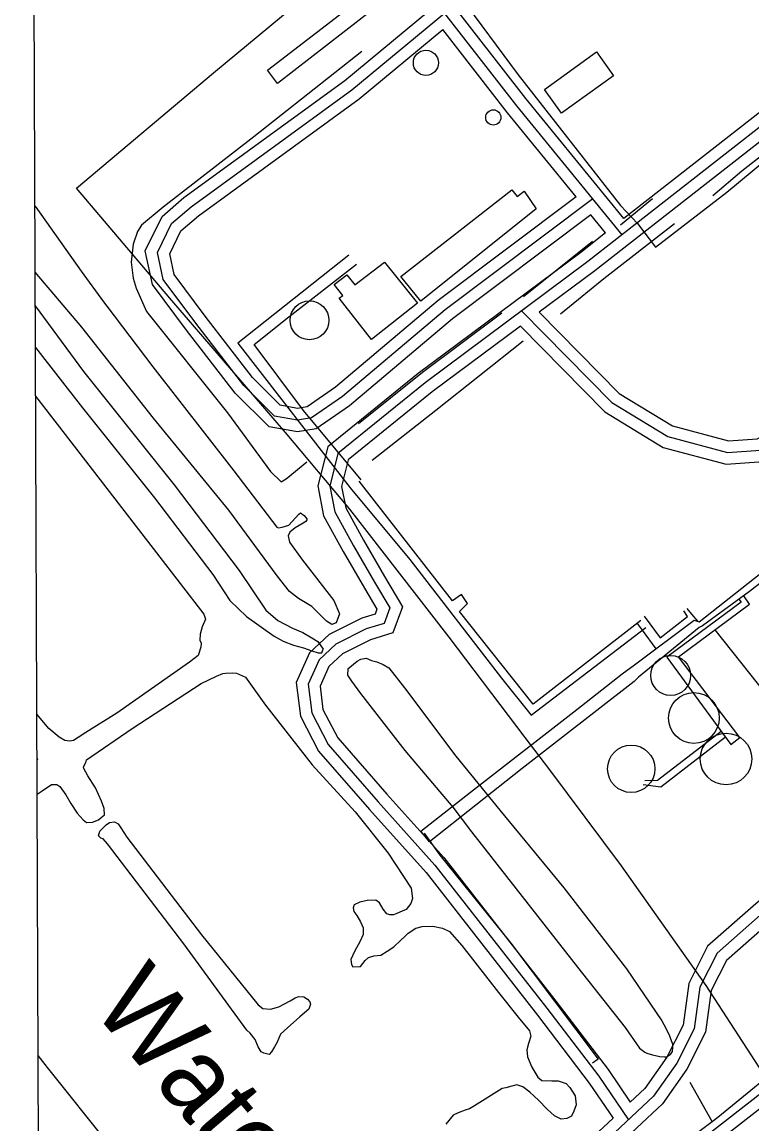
# Model space of a CAD drawing. Extents: x 3405885 to 3443815, y 558517 to 583997.
# Drawn here: x 3409954 to 3410898, y 576200 to 577623 of the extents above; entities that cross this region are included whole.
import ezdxf

# ---------------------------------------------------------------- set-up
doc = ezdxf.new("R2010")
doc.units = 0
for name, color, linetype in [('V-BLDG-OTLN', 7, 'Continuous'), ('V-DOMW-TANK', 7, 'Continuous'), ('V-GRID-FRAM', 7, 'Continuous'), ('V-RIVR-IDEN', 7, 'Continuous'), ('V-ROAD-CNTR', 7, 'Continuous'), ('V-SITE-OTLN', 7, 'Continuous'), ('V-TOPO-SHOR', 7, 'Continuous'), ('V-UTIL-LINE', 7, 'Continuous')]:
    doc.layers.add(name, color=color, linetype=linetype)

msp = doc.modelspace()

# ---------------------------------------------------------------- linework, layer by layer
at = {"layer": 'V-BLDG-OTLN'}
for points in [[(3410271.4, 577560.9), (3410397.9, 577658.9), (3410411.1, 577641.9), (3410284.4, 577543.8)], [(3410629.4, 577536.2), (3410696.7, 577584.6), (3410718.8, 577553.8), (3410651.3, 577505.4)], [(3410443.7, 577294.6), (3410587.4, 577406.5), (3410594.1, 577397.8), (3410603, 577404.7), (3410618.7, 577382.1), (3410469.4, 577262.7)], [(3410465.3, 577259.8), (3410405.6, 577213.1), (3410364, 577266.3), (3410368.6, 577269.9), (3410357.7, 577284), (3410374, 577296.8), (3410384.3, 577283.7), (3410422.6, 577313)]]:
    msp.add_lwpolyline(points, close=True, dxfattribs=at)
at = {"layer": 'V-DOMW-TANK'}
for centre, radius in [((3410476.1, 577570.5), 16.2), ((3410563.3, 577500), 9.84), ((3410325.6, 577237.9), 25.1), ((3410792.6, 576779), 25.8), ((3410822.6, 576724), 32.8), ((3410864.2, 576671.1), 33.3), ((3410741.6, 576658.4), 30.6)]:
    msp.add_circle(centre, radius, dxfattribs=at)
at = {"layer": 'V-GRID-FRAM'}
msp.add_lwpolyline([(3409954, 582088.9), (3441575.2, 582215.4), (3441655.9, 564032.2), (3410018.8, 563905.7), (3409954, 582088.9)], dxfattribs=at)
at = {"layer": 'V-ROAD-CNTR'}
for points in [[(3410729.8, 577348.3), (3410593.5, 577515.1), (3410427.7, 577728.1), (3410388.1, 577781.4), (3410372.8, 577812.5), (3410373.7, 577836.8), (3410386.6, 577857.6), (3410437.1, 577900), (3410795.1, 578180.8), (3411245.4, 578530.4), (3411873.5, 579019.9), (3412386.4, 579417.5), (3412669.1, 579639.2), (3412713.8, 579669.1), (3412750.2, 579689.7), (3412768.7, 579699.8)], [(3410732.2, 577369.2), (3410605.2, 577524.5), (3410439.7, 577737.1), (3410401, 577789.3), (3410387.9, 577815.7), (3410388.6, 577832.2), (3410398.1, 577847.7), (3410446.5, 577888.4), (3410804.3, 578169), (3411254.6, 578518.5), (3411882.7, 579008.1), (3412395.6, 579405.7), (3412677.9, 579627.1), (3412721.7, 579656.3), (3412757.5, 579676.6), (3412775.9, 579686.6)], [(3412925.9, 579068.1), (3412738, 578925.4), (3412562.6, 578790.9), (3412341.7, 578623.2), (3411769.3, 578175.8), (3411462.4, 577937.5), (3411013.6, 577589.1), (3410732.2, 577369.2)], [(3413210.3, 578015.5), (3413107.9, 577931.8), (3412854.6, 577735.4), (3412414.8, 577392.8), (3411978.8, 577052), (3411481.9, 576669), (3411109.6, 576376.2), (3410592.3, 575973.2), (3410440.1, 575851.4), (3410435.1, 575850.6)], [(3411471.6, 577925.6), (3411022.8, 577577.3), (3410685.6, 577313.7), (3410475.2, 577157.1), (3410362.5, 577065.9), (3410351.8, 577023.6), (3410358.2, 576990.3), (3410382.4, 576946.5), (3410409.7, 576899.4), (3410429.3, 576866.2), (3410422.1, 576846), (3410399, 576839.1), (3410359.7, 576819.6), (3410338.1, 576799.3), (3410324, 576767.6), (3410328.5, 576730.7), (3410349.8, 576689.8), (3410414.4, 576615.6), (3410487.9, 576534), (3410632.3, 576349.1), (3410699.6, 576261.1), (3410737.9, 576204.9), (3410737, 576207.2)], [(3410689.3, 577374.2), (3410510.6, 577239.8), (3410377.4, 577127.5), (3410334.1, 577097.8), (3410310.2, 577093.6), (3410273.3, 577100.2), (3410229.4, 577143.9), (3410166.8, 577225.2), (3410122.5, 577284.2), (3410113.4, 577327.5), (3410135.1, 577372.1), (3410163.4, 577396.4), (3410371.3, 577547.5), (3410479.5, 577637.1)], [(3410691.8, 577394.9), (3410501.2, 577251.5), (3410368.3, 577139.5), (3410328.3, 577112), (3410310.2, 577108.8), (3410280.5, 577114.1), (3410240.7, 577153.8), (3410178.7, 577234.2), (3410136.5, 577290.6), (3410129.1, 577325.6), (3410147.2, 577362.8), (3410172.7, 577384.6), (3410380.5, 577535.6), (3410500.3, 577634.8), (3410501, 577633.5)], [(3410670.3, 577397.5), (3410491.9, 577263.3), (3410359.2, 577151.4), (3410322.5, 577126.2), (3410310.2, 577124), (3410287.8, 577128.1), (3410252, 577163.8), (3410190.6, 577243.3), (3410150.5, 577296.9), (3410144.9, 577323.6), (3410159.3, 577353.4), (3410182, 577372.8), (3410389.7, 577523.8), (3410498, 577613.4)], [(3410670.3, 577397.5), (3410581.7, 577505.8), (3410498, 577613.4)], [(3410992.9, 577534.9), (3410694.7, 577301.8), (3410622.7, 577248.2)], [(3410708.5, 577350.7), (3410689.3, 577374.2)], [(3410708.5, 577350.7), (3410676.5, 577325.6), (3410466, 577169), (3410349.2, 577074.4), (3410336.5, 577024), (3410343.9, 576985.1), (3410369.3, 576939.1), (3410396.8, 576891.8), (3410412.8, 576864.6), (3410410.5, 576858.2), (3410393.5, 576853.1), (3410351, 576832.1), (3410325.6, 576808.2), (3410308.6, 576769.9), (3410314, 576726.2), (3410337.3, 576681.3), (3410403.1, 576605.7), (3410476.4, 576524.4), (3410620.5, 576340), (3410687.4, 576252.3), (3410718.3, 576207.1)], [(3410622.7, 577248.2), (3410726, 577143.5), (3410795.1, 577101.6), (3410867.4, 577082.2), (3410904.5, 577084.8), (3410952.7, 577109.5), (3411021.4, 577171.4), (3411084.2, 577228.4), (3411130.8, 577263.4), (3411180.9, 577294)], [(3410604.3, 577253.2), (3410599.9, 577250), (3410716.6, 577131.6), (3410789.1, 577087.6), (3410866, 577067), (3410908.6, 577070), (3410961.3, 577097), (3411031.4, 577160.3), (3411093.8, 577216.8), (3411139.2, 577251), (3411203, 577290), (3411201.9, 577290)], [(3410598.4, 577230.1), (3410707.3, 577119.8), (3410783.1, 577073.7), (3410864.5, 577051.9), (3410912.7, 577055.3), (3410969.9, 577084.6), (3411041.5, 577149.1), (3411103.3, 577205.2), (3411147.7, 577238.5), (3411199.4, 577270.2)], [(3410598.4, 577230.1), (3410484.4, 577145.3), (3410375.8, 577057.4), (3410367.2, 577023.1), (3410372.5, 576995.4), (3410395.4, 576953.9), (3410422.7, 576907), (3410445.7, 576867.7), (3410433.6, 576833.9), (3410404.6, 576825.1), (3410368.3, 576807.1), (3410350.6, 576790.5), (3410339.4, 576765.3), (3410343.1, 576735.2), (3410362.3, 576698.3), (3410425.6, 576625.6), (3410499.4, 576543.7), (3410644.2, 576358.3), (3410711.8, 576269.9), (3410740.4, 576227.8)], [(3411375.4, 577065.1), (3411375.8, 577066.8), (3411284.4, 576987.8), (3411176.8, 576892.7), (3411144.4, 576832), (3411121.8, 576775.8), (3411111.5, 576718), (3411095, 576658.8), (3411070.8, 576608.1), (3411017.4, 576558.9), (3410912.3, 576472.6), (3410852.5, 576420.1), (3410830.4, 576376.4), (3410823.1, 576322.5), (3410800.5, 576277.9), (3410770.6, 576235.6), (3410684.7, 576155)], [(3411355.2, 577068.8), (3411274.5, 576999.1), (3411164.8, 576902.2), (3411130.8, 576838.3), (3411107.3, 576779.9), (3411096.9, 576721.3), (3411080.9, 576664.1), (3411058.5, 576617.2), (3411007.6, 576570.3), (3410902.6, 576484.1), (3410840.4, 576429.4), (3410815.9, 576380.9), (3410808.6, 576327), (3410787.7, 576285.7), (3410759.2, 576245.5), (3410740.4, 576227.8)], [(3411373.6, 577045.1), (3411294.2, 576976.5), (3411188.7, 576883.3), (3411158.1, 576825.6), (3411136.3, 576771.6), (3411126.2, 576714.6), (3411109.1, 576653.5), (3411083, 576599.1), (3411027.3, 576547.6), (3410922, 576461.2), (3410864.6, 576410.7), (3410844.9, 576371.9), (3410837.6, 576318), (3410813.4, 576270.2), (3410782, 576225.7), (3410694.4, 576143.6), (3410516.6, 576006.7), (3410392.1, 575904.4)], [(3411590.1, 576771.3), (3411472.7, 576680.8), (3411100.3, 576388), (3410583, 575985), (3410439.1, 575869.8)], [(3410718.3, 576207.1), (3410674.9, 576166.5), (3410497.9, 576030.1), (3410342.6, 575902.6), (3410276.7, 575855.8), (3410238.5, 575819.4), (3410189.2, 575753.6), (3410121.9, 575679.2), (3410048.5, 575608.1), (3409988.5, 575544.4)]]:
    msp.add_lwpolyline(points, dxfattribs=at)
at = {"layer": 'V-SITE-OTLN'}
for points in [[(3410444.8, 577758.9), (3410595.5, 577555.1), (3410727.8, 577386.4), (3410749.5, 577363.1), (3410773.1, 577332.5), (3410865.4, 577403.3), (3410983.6, 577501.6), (3410998.3, 577514.1)], [(3410977.6, 576142.3), (3410922.8, 576248.4), (3410838.4, 576378.5), (3410729.1, 576533.2), (3410636.3, 576657.1), (3410604.5, 576698.8), (3410506.2, 576828.3), (3410377.8, 576993.7), (3410294.5, 577092.7), (3410144.9, 577266.6), (3410024.3, 577408.8), (3410201.7, 577557.7), (3410392.4, 577716.3)]]:
    msp.add_lwpolyline(points, dxfattribs=at)
at = {"layer": 'V-TOPO-SHOR'}
for p, q in [((3410727.9, 577361.1), (3410769.1, 577395.3)), ((3410602.2, 577268.7), (3410691.4, 577340.2)), ((3410341.6, 576808.3), (3410343.2, 576813)), ((3410375.4, 576787.7), (3410374.7, 576779.4)), ((3410817.5, 576253.4), (3410846.2, 576202.4))]:
    msp.add_line(p, q, dxfattribs=at)
for points in [[(3410393.2, 577585), (3410253.6, 577474.8), (3410136.5, 577384.2), (3410108.6, 577360.6), (3410103.2, 577352.7), (3410097.8, 577336.2), (3410095, 577313), (3410097.6, 577292.5), (3410101.4, 577279.3), (3410115.1, 577249.4), (3410219.5, 577118.4), (3410275.2, 577042.6), (3410289, 577029.2), (3410295.7, 577033.2), (3410322.3, 577054.8)], [(3411073.3, 577398.5), (3411013.8, 577472.9), (3410997, 577497.5), (3410991.3, 577502.8), (3410986.6, 577504), (3410979.6, 577504.1), (3410959.1, 577488.5), (3410884.7, 577430.6), (3410847.2, 577398.8)], [(3409970.8, 577385.5), (3410030.6, 577301.4), (3410059.3, 577261.8), (3410063.5, 577256.2)], [(3410797.4, 577362.4), (3410706, 577291.3), (3410650.3, 577245.6)], [(3410063.5, 577256.2), (3410123.1, 577177.7), (3410228, 577043.5), (3410283.6, 576970.5), (3410285.6, 576969.8), (3410290.5, 576970.5), (3410298.8, 576973.2), (3410312, 576987.6), (3410314.1, 576989), (3410318.9, 576985.5), (3410322.4, 576981.4), (3410322.4, 576980), (3410321, 576977.9), (3410317.5, 576975.9), (3410307.1, 576969.7), (3410300.1, 576964.2), (3410298, 576959.4), (3410300, 576951.1), (3410316.5, 576928.1), (3410356.9, 576876), (3410364.4, 576858.7), (3410360.2, 576846.9), (3410354.7, 576844.9), (3410347.8, 576849.1), (3410328.5, 576867.9), (3410311.3, 576878.4), (3410299.6, 576887.5), (3410283.9, 576907.6), (3410221.5, 576992.4), (3410124.1, 577111.3), (3410031.5, 577228.8), (3409971.1, 577299.9)], [(3409971.2, 577256.4), (3410033.5, 577171.7), (3410150.5, 577025.5), (3410234.8, 576914.6), (3410269.1, 576863.4), (3410284.8, 576849.8), (3410303.5, 576840.3), (3410317, 576834.3), (3410328.7, 576827.8), (3410336.3, 576823), (3410343.2, 576813)], [(3410388.8, 577104.7), (3410471.9, 577171), (3410574.3, 577247.7)], [(3410601.7, 577211), (3410489.1, 577121.4), (3410406.5, 577056.6)], [(3409971.4, 577202.7), (3410032, 577124.8), (3410125.1, 577008.6), (3410200.7, 576909.6), (3410222.8, 576876), (3410244.4, 576855.3), (3410280, 576829.9), (3410291.7, 576823.3), (3410305.1, 576818), (3410318, 576814.9), (3410328.6, 576810.8), (3410336.8, 576808.4)], [(3409971.6, 577139.7), (3410009.7, 577090.3), (3410128, 576937.5), (3410188.9, 576858.1), (3410191.2, 576851.7), (3410187.1, 576841.7), (3410184.1, 576832.4), (3410184, 576824.8), (3410185.8, 576820.7), (3410185.1, 576815.4), (3410181.6, 576804.9), (3410170.4, 576796.2), (3410076.4, 576730.2), (3410036.4, 576705.3), (3410026.4, 576698.9), (3410020.6, 576694.8), (3410015.3, 576694.3), (3410009.4, 576694.9), (3410001.9, 576699.1), (3409988.5, 576710.3), (3409973.1, 576729)], [(3410336.8, 576808.4), (3410341.6, 576808.3), (3410343.2, 576813)], [(3410375.4, 576787.7), (3410387.3, 576797.3), (3410392.1, 576800), (3410398.9, 576801.5)], [(3410398.9, 576801.5), (3410405.9, 576798.5), (3410412.9, 576796.7), (3410421.1, 576793.1), (3410428.1, 576789), (3410448.5, 576763), (3410514.8, 576674.6), (3410571.8, 576605), (3410654.5, 576504.8), (3410735.3, 576399.8), (3410781.2, 576332.6), (3410786.4, 576323.2), (3410791, 576313.2), (3410793.4, 576307.3), (3410795.1, 576303.2), (3410795.1, 576298.5), (3410794.4, 576293.2), (3410792.1, 576289.2)], [(3409973.5, 576625.7), (3409980.1, 576630.1), (3409992.3, 576638.2), (3409998.8, 576638.2), (3410002.7, 576635.4), (3410010.8, 576624.9), (3410017.3, 576613.4), (3410025.5, 576601.2), (3410033.1, 576592.4), (3410037.4, 576589.1), (3410045.1, 576589.6), (3410052.8, 576592.3), (3410056.1, 576595.6), (3410060.5, 576598.8), (3410060, 576607.1), (3410056.8, 576616.4), (3410049.2, 576634), (3410038.9, 576649.4), (3410034.1, 576658.7), (3410033.5, 576660.9), (3410036.3, 576666.4), (3410037.4, 576670.2), (3410096.3, 576710.4), (3410185.5, 576768.5), (3410205.3, 576778.2), (3410213.6, 576781.4), (3410216.9, 576782), (3410225.6, 576782.5), (3410231.1, 576781.9), (3410243.1, 576776.9), (3410268.7, 576740.5), (3410329, 576663.4), (3410384.5, 576602.7), (3410427.5, 576549.3), (3410457.3, 576504.1), (3410458.9, 576491), (3410456.6, 576484.4), (3410450.6, 576476.8), (3410445.6, 576474.6), (3410438.5, 576471.4), (3410434.1, 576469.7), (3410429.7, 576469.8), (3410425.8, 576470.9), (3410421, 576477), (3410416.1, 576485.2), (3410411.2, 576488.5), (3410400.2, 576488.1), (3410390.9, 576485.9), (3410383.2, 576482.7), (3410382, 576478.9), (3410383.1, 576473.9), (3410386.9, 576469), (3410391.8, 576460.7), (3410395, 576453), (3410395, 576444.2), (3410391.1, 576435.5), (3410383.9, 576422.4), (3410378.9, 576412)], [(3410374.7, 576779.4), (3410379.9, 576771.7), (3410391.5, 576755.8), (3410449.1, 576682.1), (3410510.8, 576608.9), (3410535.3, 576577.1), (3410592.9, 576503.4), (3410672, 576402), (3410733.6, 576324.1), (3410752.2, 576297.6), (3410759.2, 576292.3), (3410761.6, 576291.1), (3410769.2, 576288.7), (3410778.6, 576286.9), (3410784.4, 576286.3), (3410787.3, 576286.2), (3410792.1, 576289.2)], [(3409973.3, 576672.4), (3409974.2, 576670.6), (3409973.3, 576669.4)], [(3410244.5, 576320.8), (3410163, 576432.1), (3410064.7, 576561.5), (3410058.7, 576568.1), (3410055.9, 576568.7), (3410052.7, 576572), (3410054.4, 576578), (3410062.6, 576586.2), (3410067, 576588.9), (3410073.6, 576590), (3410078.5, 576587.2), (3410081.8, 576582.2), (3410089.4, 576570.1), (3410186.1, 576444), (3410259.5, 576353.6), (3410265.5, 576348.6), (3410275.4, 576348), (3410285.8, 576350.7), (3410300.7, 576358.8), (3410307.3, 576362.6), (3410311.7, 576364.2), (3410318.2, 576363.6), (3410323.2, 576360.8), (3410325.9, 576357.5), (3410327, 576354.2), (3410324.7, 576347.7), (3410313.1, 576337.9), (3410297.2, 576323.7), (3410288.3, 576315.6), (3410283.9, 576305.2), (3410280.5, 576299.2), (3410276.7, 576292.6), (3410273.4, 576289.4), (3410266.8, 576291), (3410263, 576292.7), (3410259.2, 576299.3), (3410255.4, 576308.7), (3410248.9, 576316.9), (3410244.5, 576320.8)], [(3410378.9, 576412), (3410379.9, 576405.4), (3410381.5, 576402.7), (3410391.4, 576403.1), (3410397.5, 576410.8), (3410401.9, 576414.6), (3410409, 576416.7), (3410417.8, 576417.8), (3410426.1, 576422.7), (3410434.9, 576428.6), (3410443.7, 576436.8), (3410448.7, 576441.7), (3410453.1, 576446), (3410463, 576452.6), (3410471.2, 576454.7), (3410484.9, 576455.2), (3410497.5, 576452.3), (3410506.8, 576448.4), (3410522.6, 576430.2), (3410569.9, 576369.6), (3410595.4, 576337.7), (3410610.1, 576320), (3410611.7, 576312.9), (3410608.9, 576303.6), (3410606.7, 576295.4), (3410607.7, 576286.1), (3410613.1, 576272.9), (3410620.7, 576260.2), (3410626.1, 576255.8), (3410638.8, 576255.2), (3410647, 576255.1), (3410657.4, 576251.7), (3410662.3, 576246.8), (3410669.3, 576235.8), (3410670.3, 576224.3), (3410667.5, 576216.1), (3410664.2, 576209.5), (3410658.2, 576206.8), (3410651, 576205.7), (3410642.3, 576210.2), (3410633, 576218.5), (3410621.6, 576230.1), (3410610.7, 576240.5), (3410601.4, 576247.7), (3410593.8, 576250), (3410587.2, 576248.4), (3410579.5, 576246.2), (3410574.6, 576245.2)], [(3411122.2, 576422.8), (3410955.7, 576291.5), (3410853.6, 576208), (3410846.2, 576202.4), (3410672.5, 576072), (3410454.8, 575899.9), (3410416.2, 575864.6)], [(3410067.6, 576171.8), (3409987.1, 576272.6), (3409974.7, 576288)], [(3410574.6, 576245.2), (3410538.8, 576222.9), (3410532.7, 576219.1), (3410526.7, 576217.5), (3410517.9, 576213.8), (3410511.3, 576211.1), (3410501.9, 576199.1)]]:
    msp.add_lwpolyline(points, dxfattribs=at)
at = {"layer": 'V-UTIL-LINE'}
msp.add_line((3410849.8, 576838.1), (3410927.9, 576739.6), dxfattribs=at)
for points in [[(3410376.6, 577321.9), (3410232.9, 577208.5), (3410378.2, 577021.3)], [(3410392.5, 577031.7), (3410317.9, 577121.2), (3410254.1, 577206.5), (3410298.9, 577242.2), (3410386.5, 577310.5)], [(3410753.9, 576849.8), (3410614.7, 576741.7), (3410519.6, 576861.6), (3410529.9, 576872), (3410522, 576883.7), (3410510.6, 576875.3), (3410390, 577029.9)], [(3411020.6, 576985.2), (3410894.4, 576887.6), (3410883.1, 576879.1), (3410833.9, 576843.1), (3410829.3, 576841.1), (3410750.9, 576776.9), (3410745.6, 576771), (3410600.8, 576658.9), (3410480.6, 576563.9), (3410469.4, 576577.9), (3410533.9, 576628.3), (3410671.3, 576735.1), (3410729.8, 576781), (3410745.7, 576792.8), (3410822.8, 576850.4), (3410829.4, 576848.4), (3411060.5, 577030.6)], [(3410378.2, 577021.3), (3410455.2, 576928.7), (3410573.9, 576775.4), (3410612.4, 576727.9), (3410760.5, 576841.1)], [(3410880.9, 576877.5), (3410883.6, 576873.5), (3410787.7, 576802.8), (3410870.3, 576689.8), (3410882, 576698.8), (3410802.5, 576803.2), (3410894.3, 576870.9), (3410887, 576882)], [(3410758.2, 576855.6), (3410779.2, 576827.5), (3410814.5, 576855.2), (3410809.5, 576862.6)], [(3410813.4, 576865.5), (3410819.7, 576858.2), (3410827.9, 576848.8)], [(3410749.3, 576846.3), (3410755.7, 576837.4), (3410773.3, 576813.4)], [(3410863.4, 576699.2), (3410780, 576634.8), (3410757.2, 576637.7)], [(3410759.1, 576643.1), (3410775.5, 576643.9), (3410857.7, 576707)], [(3410473.8, 576575.1), (3410494, 576547), (3410586.1, 576433.2), (3410699, 576283.2), (3410691.4, 576278)]]:
    msp.add_lwpolyline(points, dxfattribs=at)

# ---------------------------------------------------------------- texts
at = {"layer": 'V-RIVR-IDEN'}
msp.add_text('Water', height=100, rotation=310.3142, dxfattribs=at).set_placement((3410041.8, 576350))

doc.saveas('drawing.dxf')
